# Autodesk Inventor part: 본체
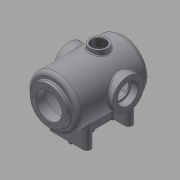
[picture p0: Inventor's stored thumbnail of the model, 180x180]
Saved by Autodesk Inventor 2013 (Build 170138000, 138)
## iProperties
Created: 2016-02
Part Number: 본체
Material: 일반
Document SubType Name: Modeling
Designer: mduedu
Density: 2.71 g/cm^3
Author: mduedu
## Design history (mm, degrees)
sketch "스케치2"
  geometry: L1 (0, 100)-(0, -100); L2 (65, -75.993)-(65, 100); L3 (65, 100)-(0, 100); A1 r 100 centre (0, 0) between (0, -100) and (65, -75.993); 2 further points
  constraints: 6 end point, 2 midpoint, 2 point on circle, 1 centre point, 1 coincident, 1 horizontal, 1 parallel, 1 vertical
  dimensions: "d3" = 200 distance of L1.start L1.end; "d5" = 130 diameter of L2 L1; "d6" = 100 radius of A1
revolve "회전1" sketch "스케치2" stored, may be unused: angle "d7" = 90 deg
sketch "스케치3"
  geometry: C1 r 47.5 at (0, 0); 1 further point
  constraints: 1 centre point, 1 coincident
  dimensions: "d8" = 95 diameter of C1
extrude "돌출2" join sketch "스케치3" distance "d10" = 10; taper "d11" = 0 deg
sketch "스케치5"
  geometry: L1 (47.5, 110)-(47.5, 100) reference; L2 (47.5, 100)-(65, 100) reference; L3 (65, 100)-(65, -75.993) reference; L4 (-65, -75.993)-(-65, 100) reference; L5 (-65, 100)-(-47.5, 100) reference; L6 (-47.5, 100)-(-47.5, 110) reference; L7 (-47.5, 110)-(47.5, 110) reference; L8 (55, 85)-(55, -71.239); L9 (0, 85)-(55, 85); L10 (0, 85)-(0, -90); A1 r 100 centre (0, 0) between (0, -100) and (65, -75.993) reference; A2 r 100 centre (0, 0) between (-65, -75.993) and (0, -100) reference; A3 r 90 centre (0, 0) between (0, -90) and (55, -71.239); 1 further point
  constraints: 6 end point, 2 point on circle, 1 centre point, 1 parallel, 1 perpendicular, 1 point on line, 1 vertical
  dimensions: "d13" = 10 distance between parallel lines of L3 L8; "d14" = 10 radial gap between concentric circles of A3 A1; "d15" = 15 distance between parallel lines of L9 L2
revolve "회전2" sketch "스케치5" stored, may be unused: angle "d16" = 90 deg
hole "구멍1" diameter "d19" = 65; stored, may be unused: countersink angle "d23" = 90 deg, drill point angle "d25" = 118 deg; dims "d17" = 10, "d18" = 10, "d20" = 6, "d21" = 4, "d22" = 2, "d24" = 8
node "작업 평면1"
sketch "스케치6"
  geometry: L1 (47.5, 110)-(-47.5, 110) reference; C1 r 40 at (0, -17); 1 further point
  constraints: 1 centre point, 1 vertical alignment
  dimensions: "d27" = 80 diameter of C1; "d29" = 127 distance from line of C1.centre L1
extrude "돌출3" join sketch "스케치6" stored distance "d30" = 10; taper "d31" = 0 deg
hole "구멍2" diameter "d34" = 42; stored, may be unused: countersink angle "d38" = 90 deg, drill point angle "d40" = 118 deg; dims "d32" = 10, "d33" = 10, "d35" = 6, "d36" = 52, "d37" = 18, "d39" = 8
sketch "스케치7" dims "d41" = 65
  geometry: C1 r 40 at (0, 0) reference; 3 further points
  constraints: 2 vertical alignment, 1 coincident, 2 other
hole "구멍3" sketch "스케치7" at (0, 32.5) diameter "d43" = 3.242; stored, may be unused: countersink angle "d47" = 90 deg, drill point angle "d49" = 118 deg; dims "d44" = 11, "d45" = 13, "d46" = 18, "d48" = 13
sketch "스케치8" dims "d53" = 80
  geometry: 3 further points
  constraints: 2 vertical alignment, 1 coincident, 2 other
hole "구멍4" sketch "스케치8" at (0, 40) diameter "d56" = 3.242; stored, may be unused: countersink angle "d60" = 90 deg, drill point angle "d62" = 118 deg; dims "d57" = 11, "d58" = 13, "d59" = 18, "d61" = 13
fillet "모깎기1" dims "d66" = 10
fillet "모깎기2" dims "d67" = 3
fillet "모깎기3" dims "d68" = 0.3
chamfer "모따기1" distance "d69" = 1; stored, may be unused: second distance "d70" = 2, angle "d71" = 45 deg
node "작업 평면5"
sketch "스케치10"
  geometry: L1 (-50, -63)-(50, -63); L2 (50, -63)-(50, -43); L3 (50, -43)-(-50, -43); L4 (-50, -43)-(-50, -63); L5 (-50, 0)-(50, 0); L6 (-50, 63)-(50, 63); L7 (50, 63)-(50, 43); L8 (50, 43)-(-50, 43); L9 (-50, 43)-(-50, 63); 2 further points
  constraints: 18 end point, 4 symmetric about line, 2 parallel, 2 perpendicular, 1 coincident, 1 horizontal, 1 midpoint
  dimensions: "d80" = 20 distance of L3.end L1.start; "d82" = 100 distance of L1.start L1.end; "d130" = 43 vertical distance of L3.end point (0, 0); "d131" = 50 horizontal distance of L3.end point (0, 0); "d132" = 100 distance of L5.start L5.end
extrude "돌출5" join sketch "스케치10" stored distance "d84" = 10; taper "d85" = 0 deg
sketch "스케치11"
  geometry: L1 (-100, -43)-(-100, 43); L2 (-65, 90)-(-65, -71.239) reference; L3 (-100, -43)-(-41.533, -43) reference; L4 (-100, 43)-(-41.533, 43) reference; 1 further point
  constraints: 2 end point, 1 point on line, 1 vertical
feature "리브1" sketch "스케치11" dims "d88" = 1, "d89" = 20, "d90" = 0, "d91" = 0, "d92" = 1, "d93" = 1
fillet "모깎기12"
fillet "모깎기13"
fillet "모깎기14"
fillet "모깎기15"
fillet "모깎기16" dims "d167" = 3
fillet "모깎기17" dims "d168" = 3
node "작업 평면6"
sketch "스케치19"
  geometry: L1 (75, -57)-(75, 23) reference; L2 (-75, -57)-(-75, 23) reference; L3 (75, -17)-(-75, -17); C1 r 22.5 at (0, -17); 1 further point
  constraints: 3 midpoint, 2 end point, 1 centre point
  dimensions: "d149" = 45 diameter of C1
extrude "돌출11" join sketch "스케치19" stored distance "d150" = 10; taper "d151" = 0 deg
hole "구멍6" diameter "d154" = 35; stored, may be unused: countersink angle "d158" = 90 deg, drill point angle "d160" = 118 deg; dims "d152" = 10, "d153" = 10, "d155" = 6, "d156" = 4, "d157" = 2, "d159" = 8
fillet "모깎기11" dims "d161" = 3
feature "스레드1" dims "d162" = 10, "d163" = 0
chamfer "모따기3" distance "d164" = 1; stored, may be unused: second distance "d165" = 2, angle "d166" = 45 deg
sketch "스케치20"
  geometry: L1 (10, 40)-(10, -40) reference; L2 (13, -43)-(40, -43) reference; L3 (40, -63)-(-40, -63) reference; L4 (-40, -43)-(-13, -43) reference; L5 (-10, -40)-(-10, 40) reference; L6 (-13, 43)-(-40, 43) reference; L7 (-40, 63)-(40, 63) reference; L8 (40, 43)-(13, 43) reference; L9 (-40, 53)-(40, 53); L10 (-40, -53)-(40, -53); L11 (0, 53)-(0, -53); C1 r 5 at (0, 53); C2 r 5 at (0, 0); C3 r 5 at (0, -53); A1 r 3 centre (13, -40) between (10, -40) and (13, -43) reference; A2 r 10 centre (40, -53) between (40, -63) and (40, -43) reference; A3 r 10 centre (-40, -53) between (-40, -43) and (-40, -63) reference; A4 r 3 centre (-13, -40) between (-13, -43) and (-10, -40) reference; A5 r 3 centre (-13, 40) between (-10, 40) and (-13, 43) reference; A6 r 10 centre (-40, 53) between (-40, 63) and (-40, 43) reference; A7 r 10 centre (40, 53) between (40, 43) and (40, 63) reference; A8 r 3 centre (13, 40) between (13, 43) and (10, 40) reference; 1 further point
  constraints: 6 end point, 3 centre point, 3 coincident, 2 midpoint, 2 parallel
  dimensions: "d169" = 10 diameter of C1; "d170" = 10 diameter of C2; "d171" = 10 diameter of C3
extrude "돌출12" join sketch "스케치20" distance "d172" = 10; taper "d173" = 0 deg
chamfer "모따기4" distance "d174" = 1; stored, may be unused: second distance "d175" = 2, angle "d176" = 45 deg
node "솔리드2"
pattern_circular "원형 패턴1" dims angle "d51" = 360 deg
mirror "대칭1"
pattern_circular "원형 패턴2" dims angle "d64" = 360 deg
node "절단 모서리 투영1"
node "절단 모서리 투영4"
other parameters: "d26" = 75, "d136" = 175
